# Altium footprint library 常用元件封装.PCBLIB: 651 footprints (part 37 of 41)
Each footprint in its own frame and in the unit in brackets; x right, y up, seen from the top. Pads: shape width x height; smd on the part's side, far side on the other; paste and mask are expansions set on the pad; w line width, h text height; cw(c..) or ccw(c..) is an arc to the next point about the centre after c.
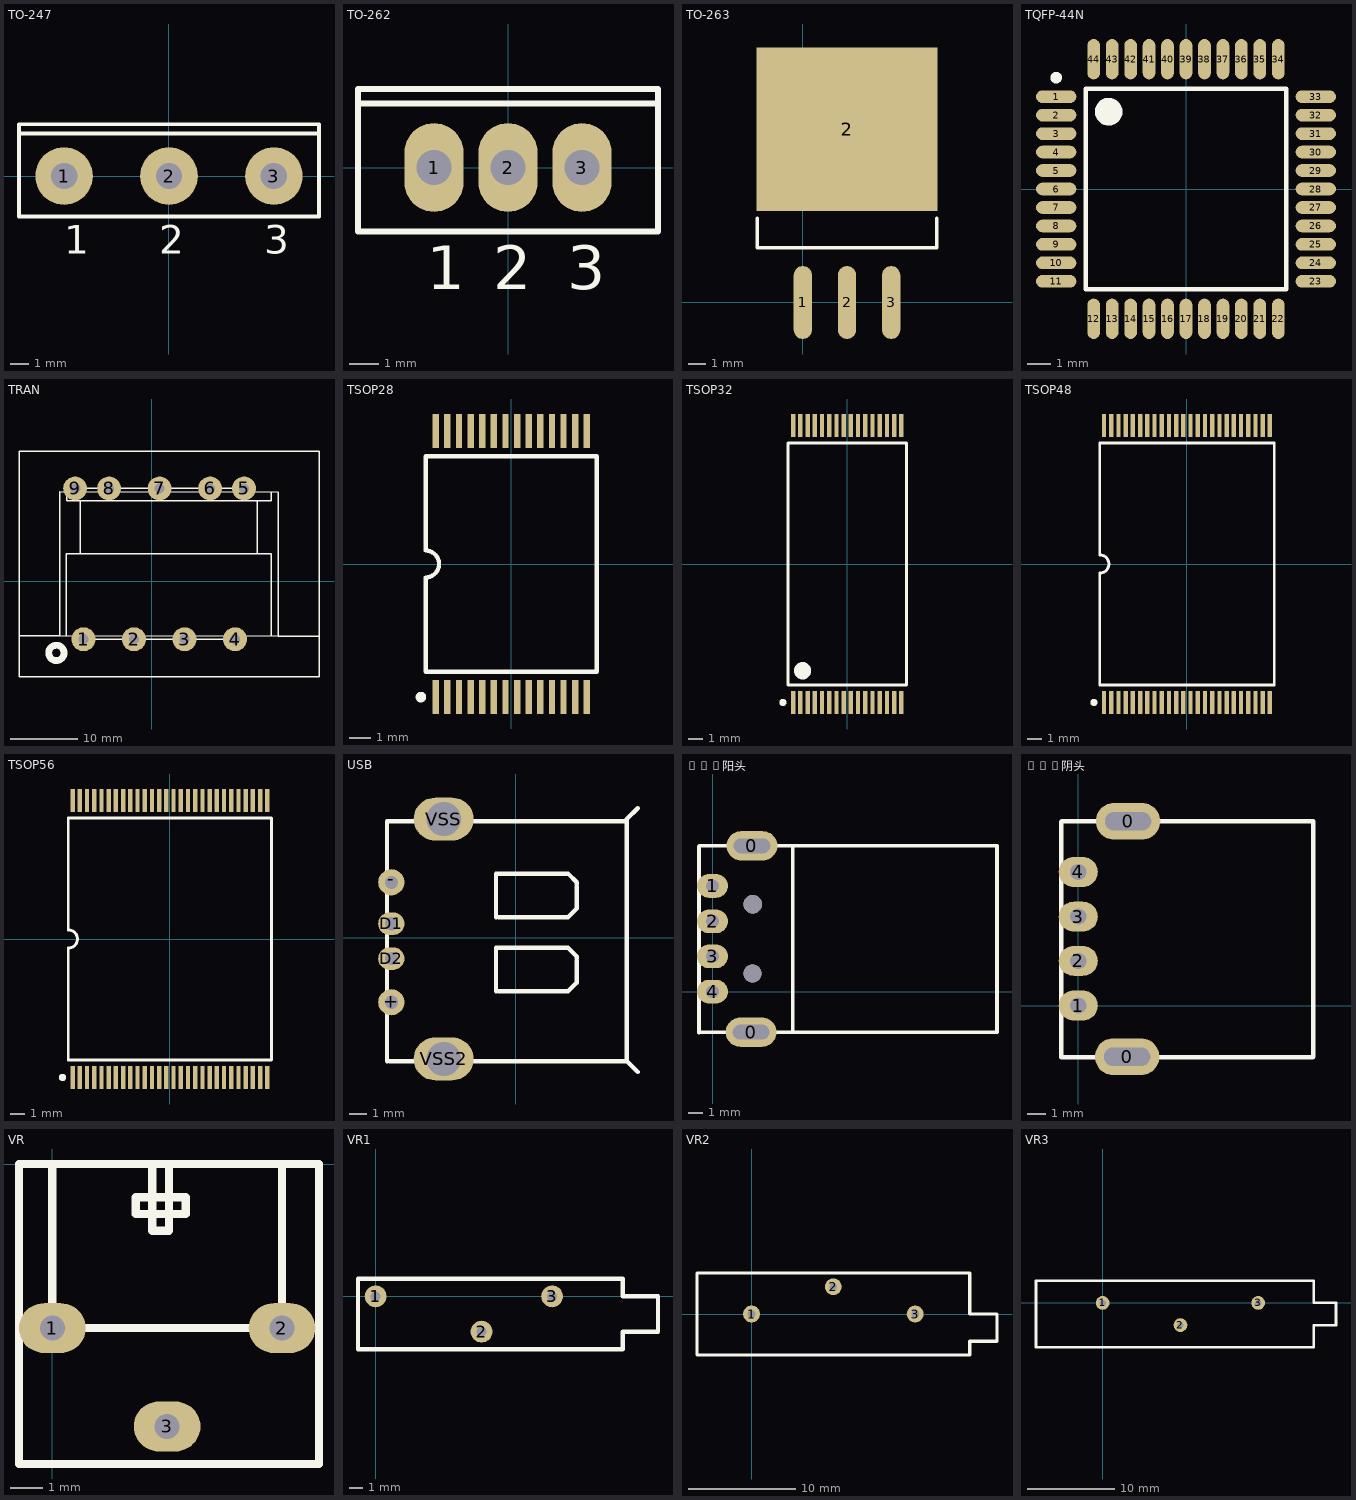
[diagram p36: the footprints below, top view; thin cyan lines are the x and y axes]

## TO-247 [mil] "SIP with Mounting Hole; 3 Leads; Body 20.6 x 15.6 x 4.7 mm (typ); Pitch 5.56 mm"
height 976.38
pads (3):
  round 120 hole 55.12: 1(-218.9,0) 2(0,0) 3(218.9,0)
TopOverlay:
  lines w7.87: -312.99,88.58 310.63,88.58 ; -312.99,-84.65 -312.99,108.27 312.99,108.27 312.99,-84.65 -312.99,-84.65
  text "3" at 198.9,-162.4 h59.06
  text "2" at -20,-162.4 h59.06
  text "1" at -218.9,-162.4 h59.06

## TO-262 [mil] "TO, Thru-Hole, Vertical, Heatsink Mounted; 3 In-Line Leads; Pitch 2.54 mm"
height 555.12
pads (3):
  oval 80x120 hole 47.24: 1(-100,0) 2(0,0) 3(100,0)
TopOverlay:
  lines w7.87: -202.76,86.61 202.76,86.61 ; -202.76,-86.61 202.76,-86.61 202.76,106.3 -202.76,106.3 -202.76,-86.61
  text "1" at -109.84,-164.37 h59.06
  text "2" at -19.68,-164.37 h59.06
  text "3" at 80.31,-164.37 h59.06

## TO-263 [mm] "D2-PAK, 4-Pads, Body 9.4x10.3mm (max), IPC Medium Density"
height 4.83
pads (4):
  oval 1.05x4.2 smd: 1(0,0) 2(2.54,0) 3(5.08,0)
  rect 10.4x9.4 smd: 2(2.54,9.95)
TopOverlay:
  lines w0.2: -2.61,4.85 -2.61,3.15 7.69,3.15 7.69,4.85

## TQFP-44N [mm] "TQFP, 44-Leads, Body 12.3x12.3mm (max), Pitch 0.80mm"
height 1.2
pads (44):
  oval 1.75x0.55 smd: 1(-5.625,4) 2(-5.625,3.2) 3(-5.625,2.4) 4(-5.625,1.6) 5(-5.625,0.8) 6(-5.625,0) 7(-5.625,-0.8) 8(-5.625,-1.6) 9(-5.625,-2.4) 10(-5.625,-3.2) 11(-5.625,-4) 23(5.625,-4) 24(5.625,-3.2) 25(5.625,-2.4) 26(5.625,-1.6) 27(5.625,-0.8) 28(5.625,0) 29(5.625,0.8) 30(5.625,1.6) 31(5.625,2.4) 32(5.625,3.2) 33(5.625,4)
  oval 0.55x1.75 smd: 12(-4,-5.625) 13(-3.2,-5.625) 14(-2.4,-5.625) 15(-1.6,-5.625) 16(-0.8,-5.625) 17(0,-5.625) 18(0.8,-5.625) 19(1.6,-5.625) 20(2.4,-5.625) 21(3.2,-5.625) 22(4,-5.625) 34(4,5.625) 35(3.2,5.625) 36(2.4,5.625) 37(1.6,5.625) 38(0.8,5.625) 39(0,5.625) 40(-0.8,5.625) 41(-1.6,5.625) 42(-2.4,5.625) 43(-3.2,5.625) 44(-4,5.625)
TopOverlay:
  circle w0.6: c-3.35,3.35 r0.3
  circle w0.25: c-5.625,4.825 r0.125
  lines w0.2: -4.35,-4.35 4.35,-4.35 4.35,4.35 -4.35,4.35 -4.35,-4.35

## TRAN [mil]
pads (9):
  round 140 hole 60: 1(-400,-340) 2(-104,-340) 3(192,-340) 4(488,-340) 5(541,544) 6(342,544) 7(46,544) 8(-250,544) 9(-449,544)
TopOverlay:
  circle w40: c-559.1,-420 r45.1
  lines w8: -778,-319 -540,-319 ; -500,-318 -500,160 -460,160 660,160 699,160 699,-321 ; -498,523 -498,471 698,471 699,472 699,521 ; -450,544 541,544 ; -420,160 -420,469 ; -402,-340 488,-340 ; 617,160 617,470 ; 980,-321 742,-321 ; -540,-319 742,-321 ; -540,-319 -540,523 742,521 742,-321 ; -778,-561 -778,763 980,763 980,-561 -778,-561

## TSOP28 [mm] "Shrink Small Outline, Plastic, Thin; 28 Leads; Body Width 11.8 mm; Pitch 0.55 mm"
height 1.2
pads (28):
  rect 0.3x1.6 smd: 1(0.275,-6.3) 2(0.825,-6.3) 3(1.375,-6.3) 4(1.925,-6.3) 5(2.475,-6.3) 6(3.025,-6.3) 7(3.575,-6.3) 8(3.575,6.3) 9(3.025,6.3) 10(2.475,6.3) 11(1.925,6.3) 12(1.375,6.3) 13(0.825,6.3) 14(0.275,6.3) 15(-0.275,6.3) 16(-0.825,6.3) 17(-1.375,6.3) 18(-1.925,6.3) 19(-2.475,6.3) 20(-3.025,6.3) 21(-3.575,6.3) 22(-3.575,-6.3) 23(-3.025,-6.3) 24(-2.475,-6.3) 25(-1.925,-6.3) 26(-1.375,-6.3) 27(-0.825,-6.3) 28(-0.275,-6.3)
TopOverlay:
  circle w0.25: c-4.275,-6.3 r0.125
  lines w0.2: -4.05,-5.1 4.05,-5.1 4.05,5.1 -4.05,5.1 -4.05,0.635 cw(c-4.05,0) -4.05,-0.635 -4.05,-5.1

## TSOP32 [mm] "Shrink Small Outline, Plastic, Thin; 32 Leads; Body Width 18.4 mm; Pitch 0.5 mm"
height 1.2
pads (32):
  rect 0.3x1.6 smd: 1(-3.75,-9.6) 2(-3.25,-9.6) 3(-2.75,-9.6) 4(-2.25,-9.6) 5(-1.75,-9.6) 6(-1.25,-9.6) 7(-0.75,-9.6) 8(-0.25,-9.6) 9(0.25,-9.6) 10(0.75,-9.6) 11(1.25,-9.6) 12(1.75,-9.6) 13(2.25,-9.6) 14(2.75,-9.6) 15(3.25,-9.6) 16(3.75,-9.6) 17(3.75,9.6) 18(3.25,9.6) 19(2.75,9.6) 20(2.25,9.6) 21(1.75,9.6) 22(1.25,9.6) 23(0.75,9.6) 24(0.25,9.6) 25(-0.25,9.6) 26(-0.75,9.6) 27(-1.25,9.6) 28(-1.75,9.6) 29(-2.25,9.6) 30(-2.75,9.6) 31(-3.25,9.6) 32(-3.75,9.6)
TopOverlay:
  circle w0.25: c-4.46,-9.6 r0.125
  circle w0.6: c-3.1,-7.4 r0.3
  lines w0.2: -4.1,-8.4 -4.1,-0.635 -4.1,8.4 4.1,8.4 4.1,-8.4 -4.1,-8.4

## TSOP48 [mm] "Shrink Small Outline, Plastic, Thin; 48 Leads; Body Width 18.4 mm; Pitch 0.5 mm"
height 1.2
pads (48):
  rect 0.3x1.6 smd: 1(-5.75,-9.6) 2(-5.25,-9.6) 3(-4.75,-9.6) 4(-4.25,-9.6) 5(-3.75,-9.6) 6(-3.25,-9.6) 7(-2.75,-9.6) 8(-2.25,-9.6) 9(-1.75,-9.6) 10(-1.25,-9.6) 11(-0.75,-9.6) 12(-0.25,-9.6) 13(0.25,-9.6) 14(0.75,-9.6) 15(1.25,-9.6) 16(1.75,-9.6) 17(2.25,-9.6) 18(2.75,-9.6) 19(3.25,-9.6) 20(3.75,-9.6) 21(4.25,-9.6) 22(4.75,-9.6) 23(5.25,-9.6) 24(5.75,-9.6) 25(5.75,9.6) 26(5.25,9.6) 27(4.75,9.6) 28(4.25,9.6) 29(3.75,9.6) 30(3.25,9.6) 31(2.75,9.6) 32(2.25,9.6) 33(1.75,9.6) 34(1.25,9.6) 35(0.75,9.6) 36(0.25,9.6) 37(-0.25,9.6) 38(-0.75,9.6) 39(-1.25,9.6) 40(-1.75,9.6) 41(-2.25,9.6) 42(-2.75,9.6) 43(-3.25,9.6) 44(-3.75,9.6) 45(-4.25,9.6) 46(-4.75,9.6) 47(-5.25,9.6) 48(-5.75,9.6)
TopOverlay:
  circle w0.25: c-6.45,-9.6 r0.125
  lines w0.2: -6.05,-8.4 -6.05,-0.635 ccw(c-6.05,0) -6.05,0.635 -6.05,8.4 6.05,8.4 6.05,-8.4 -6.05,-8.4

## TSOP56 [mm] "Shrink Small Outline, Plastic, Thin; 56 Leads; Body Width 18.4 mm; Pitch 0.5 mm"
height 1.2
pads (56):
  rect 0.3x1.6 smd: 1(-6.75,-9.6) 2(-6.25,-9.6) 3(-5.75,-9.6) 4(-5.25,-9.6) 5(-4.75,-9.6) 6(-4.25,-9.6) 7(-3.75,-9.6) 8(-3.25,-9.6) 9(-2.75,-9.6) 10(-2.25,-9.6) 11(-1.75,-9.6) 12(-1.25,-9.6) 13(-0.75,-9.6) 14(-0.25,-9.6) 15(0.25,-9.6) 16(0.75,-9.6) 17(1.25,-9.6) 18(1.75,-9.6) 19(2.25,-9.6) 20(2.75,-9.6) 21(3.25,-9.6) 22(3.75,-9.6) 23(4.25,-9.6) 24(4.75,-9.6) 25(5.25,-9.6) 26(5.75,-9.6) 27(6.25,-9.6) 28(6.75,-9.6) 29(6.75,9.6) 30(6.25,9.6) 31(5.75,9.6) 32(5.25,9.6) 33(4.75,9.6) 34(4.25,9.6) 35(3.75,9.6) 36(3.25,9.6) 37(2.75,9.6) 38(2.25,9.6) 39(1.75,9.6) 40(1.25,9.6) 41(0.75,9.6) 42(0.25,9.6) 43(-0.25,9.6) 44(-0.75,9.6) 45(-1.25,9.6) 46(-1.75,9.6) 47(-2.25,9.6) 48(-2.75,9.6) 49(-3.25,9.6) 50(-3.75,9.6) 51(-4.25,9.6) 52(-4.75,9.6) 53(-5.25,9.6) 54(-5.75,9.6) 55(-6.25,9.6) 56(-6.75,9.6)
TopOverlay:
  circle w0.25: c-7.45,-9.6 r0.125
  lines w0.2: -7.05,-8.4 7.05,-8.4 7.05,8.4 -7.05,8.4 -7.05,0.635 cw(c-7.05,0) -7.05,-0.635 -7.05,-8.4

## USB [mm]
pads (6):
  round 1.524 hole 0.762: +(-7.255,-3.757) -(-7.255,3.228)
  oval 1.524x1.324 hole 0.762: D1(-7.255,0.815) D2(-7.255,-1.217)
  oval 3.5x2.5 hole 2: VSS(-4.207,6.911) VSS2(-4.207,-7.059)
TopOverlay:
  lines w0.254: -7.509,-7.186 -7.509,6.784 6.461,6.784 ; -7.382,-7.186 6.461,-7.186 ; -1.159,-3.122 -1.159,-0.582 3.032,-0.582 3.54,-1.09 3.54,-1.217 ; -1.159,1.196 -1.159,3.736 3.032,3.736 3.54,3.228 3.54,3.101 ; -1.032,-3.122 3.032,-3.122 3.54,-2.614 3.54,-1.344 ; -1.032,1.196 3.032,1.196 3.54,1.704 3.54,2.974 ; 7.096,-7.821 6.461,-7.186 ; 7.096,7.546 6.461,6.911 6.461,6.784 ; 6.461,-7.186 6.461,6.784

## USB阳头 [mil]
pads (6):
  oval 140x80 hole 40 slot 100 at 0 deg: 0(106,-111) 0(108,400)
  oval 85x65 hole 35: 1(0,290) 2(0,193) 3(0,97) 4(0,0)
via 110,50 diameter 50 hole 50
via 110,240 diameter 51 hole 51
TopOverlay:
  lines w10: 220,-111.57 780,-111.57 780,400 220,400 ; 220,-111.57 220,400 ; 220,-111.57 -37,-112 -37,399 -36,400 220,400

## USB阴头 [mil]
pads (6):
  oval 140x80 hole 40 slot 100 at 0 deg: 0(106,-111) 0(108,400)
  oval 85x65 hole 35: 1(0,0) 2(0,97) 3(0,193) 4(0,290)
TopOverlay:
  lines w10: 509.08,-112 -37,-112 -37,399 -36,400 510,400 510,-111.08

## VR [mil]
pads (3):
  oval 80x60 hole 30: 1(0,-196.85) 2(275.59,-196.85) 3(137.8,-314.96)
TopOverlay:
  lines w10: 120,0 120,-80 140,-80 140,0 ; 0,0 -40,0 -40,-360 320,-360 320,-300 320,0 275.59,0 ; 0,0 0,-196.85 275.59,-196.85 275.59,0 ; 0,0 275.59,0 ; 100,-60 100,-40 160,-40 160,-60 100,-60

## VR1 [mil]
pads (3):
  round 62 hole 28: 1(0,0) 2(300,-100) 3(500,0)
TopOverlay:
  lines w12: -50,-150 -50,50 700,50 700,0 800,0 800,-100 700,-100 700,-150 -50,-150

## VR2 [mil]
pads (3):
  round 62 hole 28: 1(0,0) 2(300,100) 3(600,0)
TopOverlay:
  lines w12: -200,-150 -200,150 800,150 800,0 900,0 900,-100 800,-100 800,-150 -200,-150

## VR3 [mil]
pads (3):
  round 62 hole 28: 1(0,0) 2(350,-100) 3(700,0)
TopOverlay:
  lines w12: -300,-200 -300,100 950,100 950,0 1050,0 1050,-100 950,-100 950,-200 -300,-200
